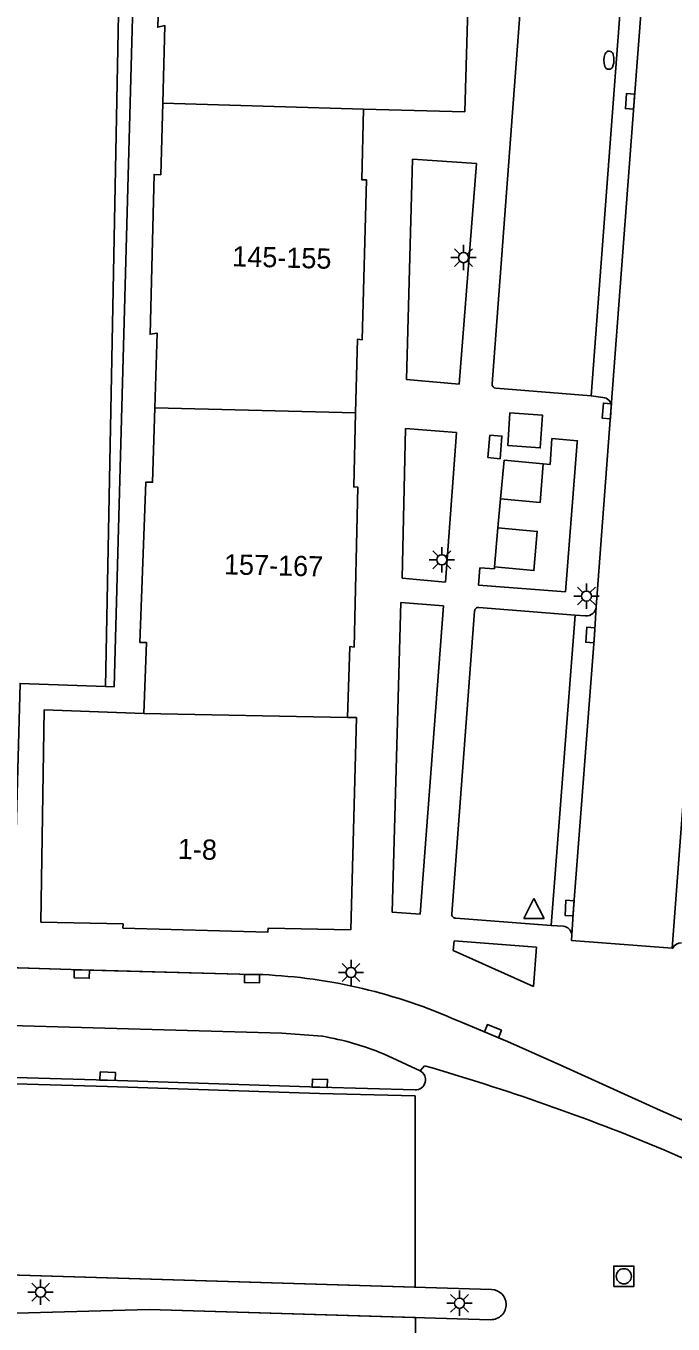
# Model space of a CAD drawing. Extents: x 132573 to 132944, y 398226 to 398676.
# Drawn here: x 132785.5 to 132817.6, y 398277.6 to 398341.8 of the extents above; entities that cross this region are included whole.
import ezdxf

# ---------------------------------------------------------------- set-up
doc = ezdxf.new("R2010")
doc.units = 0
for name, color, linetype in [('gg-anno-huisnummerreeks BGT', 7, 'Continuous'), ('gg-bbg-hoofdgebouw', 7, 'Continuous'), ('gg-bbg-tussenscheiding', 7, 'Continuous'), ('gg-knt-verharding', 7, 'Continuous'), ('gg-knt-verharding nz', 7, 'Continuous'), ('gg-kwrk-afval apart plaats', 7, 'Continuous'), ('gt-grn-groengrens', 7, 'Continuous'), ('gt-symb-brandkraan', 7, 'Continuous'), ('gt-symb-kolk', 7, 'Continuous'), ('gt-symb-lichtmast', 7, 'Continuous'), ('gt-symb-rioolschacht', 7, 'Continuous'), ('gt-symb-waterafsluiter', 7, 'Continuous'), ('ir-asfa-asfalt arcering', 7, 'Continuous'), ('ir-asfa-asfalt rood', 7, 'Continuous')]:
    doc.layers.add(name, color=color, linetype=linetype)

msp = doc.modelspace()

# ---------------------------------------------------------------- linework, layer by layer
at = {"layer": 'gg-bbg-hoofdgebouw'}
for p, q in [((132807.26, 398337.57), (132807.56, 398348.04)), ((132802.25, 398337.71), (132807.26, 398337.57))]:
    msp.add_line(p, q, dxfattribs=at)
for points in [[(132798.495, 398348.532), (132796.16, 398348.6), (132796.15, 398348.37), (132792.26, 398348.48), (132792.06, 398341.76), (132792.42, 398341.84), (132792.311, 398338)], [(132792.311, 398338), (132792.21, 398334.47), (132791.88, 398334.48), (132791.68, 398326.58), (132792.03, 398326.64), (132791.92, 398322.944)], [(132801.855, 398322.685), (132801.95, 398326.34), (132802.18, 398326.31), (132802.39, 398334.22), (132802.16, 398334.22), (132802.25, 398337.71)], [(132791.92, 398322.944), (132791.81, 398319.26), (132791.48, 398319.27), (132791.18, 398311.34), (132791.51, 398311.33), (132791.38, 398307.82)], [(132801.45, 398307.63), (132801.57, 398311.13), (132801.78, 398311.11), (132801.96, 398319.02), (132801.76, 398319.03), (132801.855, 398322.685)], [(132791.38, 398307.82), (132786.44, 398308), (132786.28, 398297.5)], [(132801.45, 398307.63), (132801.89, 398307.62), (132801.61, 398297.12)], [(132801.61, 398297.12), (132797.53, 398297.21), (132797.51, 398297.01), (132790.34, 398297.21), (132790.35, 398297.42), (132786.28, 398297.5)]]:
    msp.add_lwpolyline(points, dxfattribs=at)
at = {"layer": 'gg-bbg-tussenscheiding'}
for p, q in [((132792.311, 398338), (132802.25, 398337.71)), ((132801.855, 398322.685), (132791.92, 398322.944)), ((132801.45, 398307.63), (132791.38, 398307.82))]:
    msp.add_line(p, q, dxfattribs=at)
at = {"layer": 'gg-knt-verharding'}
for p, q in [((132808.606, 398324.128), (132810.414, 398348.064)), ((132807.835, 398335.016), (132806.983, 398324.106)), ((132806.983, 398324.106), (132804.368, 398324.337)), ((132813.517, 398323.528), (132808.787, 398323.908)), ((132814.086, 398323.443), (132813.517, 398323.528)), ((132813.756, 398313.104), (132814.506, 398323.009)), ((132804.151, 398314.509), (132804.321, 398321.924)), ((132804.321, 398321.924), (132806.853, 398321.727)), ((132806.853, 398321.727), (132806.303, 398314.323)), ((132808.394, 398320.477), (132808.49, 398321.585)), ((132809.011, 398320.425), (132808.394, 398320.477)), ((132809.027, 398318.444), (132809.197, 398320.346)), ((132808.897, 398317.005), (132809.027, 398318.444)), ((132808.727, 398315.078), (132808.897, 398317.005)), ((132807.929, 398314.169), (132807.993, 398315.03)), ((132806.303, 398314.323), (132804.151, 398314.509)), ((132804.083, 398313.316), (132806.194, 398313.148)), ((132806.194, 398313.148), (132805.042, 398297.892)), ((132806.613, 398297.913), (132807.74, 398312.883)), ((132807.954, 398313.068), (132812.714, 398312.686)), ((132812.714, 398312.686), (132813.237, 398312.652)), ((132811.531, 398297.341), (132806.806, 398297.697)), ((132812.122, 398297.307), (132811.531, 398297.341)), ((132812.542, 398296.601), (132812.556, 398296.871)), ((132806.738, 398296.584), (132806.686, 398296.101)), ((132810.809, 398296.265), (132806.738, 398296.584)), ((132810.655, 398294.324), (132810.809, 398296.265)), ((132817.512, 398296.226), (132812.542, 398296.601)), ((132817.546, 398296.223), (132817.512, 398296.226)), ((132806.686, 398296.101), (132810.655, 398294.324)), ((132803.229, 398290.985), (132805.05, 398290.153)), ((132816.942, 398288.197), (132812.1, 398290.375)), ((132808.578, 398279.341), (132774.34, 398280.37))]:
    msp.add_line(p, q, dxfattribs=at)
for points in [[(132798.535, 398349.903), (132791.03, 398350.08), (132789.91, 398309.15), (132789.475, 398309.165)], [(132804.368, 398324.337), (132804.67, 398335.236), (132807.835, 398335.016)], [(132812.819, 398321.236), (132812.237, 398313.844), (132807.929, 398314.169)], [(132808.49, 398321.585), (132809.096, 398321.543), (132809.011, 398320.425)], [(132812.819, 398321.236), (132812.826, 398321.313), (132811.569, 398321.42), (132811.475, 398320.145), (132811.133, 398320.17)], [(132807.993, 398315.03), (132808.718, 398314.983), (132808.727, 398315.078)], [(132805.042, 398297.892), (132803.659, 398298.006), (132804.083, 398313.316)], [(132789.475, 398309.165), (132785.25, 398309.31), (132784.948, 398297.791)], [(132797.256, 398294.91), (132796.729, 398294.913), (132788.309, 398295.144), (132774.193, 398295.587)], [(132774.846, 398292.671), (132798.199, 398292.017), (132800.206, 398291.863)], [(132812.1, 398290.375), (132809.366, 398291.605), (132806.922, 398292.621)], [(132774.802, 398290.113), (132789.578, 398289.684), (132800.077, 398289.337), (132804.804, 398289.208)], [(132824.492, 398284.677), (132818.145, 398287.656), (132816.942, 398288.197)], [(132774.29, 398277.87), (132791.63, 398278.35), (132808.533, 398277.845)]]:
    msp.add_lwpolyline(points, dxfattribs=at)
for centre, radius, start, end in [((132808.816, 398324.116), 0.21, 176.82394, 262.06619), ((132814.089, 398323.026), 0.417, 357.66363, 90.45799), ((132807.932, 398312.877), 0.192, 83.43793, 178.24798), ((132813.268, 398313.14), 0.489, 266.33665, 355.76893), ((132806.807, 398297.893), 0.196, 173.99977, 269.56299), ((132812.063, 398296.814), 0.496, 6.57919, 83.15738), ((132817.96, 398296.018), 0.462, 87.45576, 153.69382), ((132796.078, 398268.383), 26.553, 65.89662, 87.45786), ((132797.925, 398278.365), 13.69, 67.20244, 80.40674), ((132804.809, 398289.711), 0.503, 269.45289, 61.36461), ((132808.554, 398278.592), 0.749, 2.1288, 88.18819), ((132808.554, 398278.594), 0.749, 268.35794, 2.0129)]:
    msp.add_arc(centre, radius, start, end, dxfattribs=at)
at = {"layer": 'gg-knt-verharding nz'}
for p, q in [((132813.517, 398323.528), (132815.337, 398347.889)), ((132817.512, 398296.226), (132818.81, 398313.33)), ((132811.531, 398297.341), (132812.714, 398312.686)), ((132805.05, 398290.153), (132805.266, 398290.404)), ((132817.108, 398286.251), (132822.579, 398283.821))]:
    msp.add_line(p, q, dxfattribs=at)
for points in [[(132814.506, 398323.009), (132815.632, 398338.083), (132816.386, 398347.808)], [(132812.556, 398296.871), (132812.637, 398298.186), (132813.667, 398311.69), (132813.756, 398313.104)]]:
    msp.add_lwpolyline(points, dxfattribs=at)
msp.add_arc((132773.592, 398181.128), 113.774, 67.51276, 73.83561, dxfattribs=at)
at = {"layer": 'gg-kwrk-afval apart plaats'}
msp.add_line((132809.197, 398320.346), (132811.133, 398320.17), dxfattribs=at)
for points in [[(132809.492, 398322.687), (132811.105, 398322.574), (132810.989, 398320.96), (132809.379, 398321.079), (132809.492, 398322.687)], [(132811.133, 398320.17), (132810.99, 398318.266), (132809.027, 398318.444)], [(132808.727, 398315.078), (132810.679, 398314.895), (132810.838, 398316.829), (132808.897, 398317.005)]]:
    msp.add_lwpolyline(points, dxfattribs=at)
at = {"layer": 'gt-grn-groengrens'}
msp.add_line((132790.288, 398350.798), (132789.475, 398309.165), dxfattribs=at)
at = {"layer": 'gt-symb-brandkraan'}
for centre, radius, start, end in [((132814.396, 398340.374), 0.206, 15.97693, 160.84307), ((132815.079, 398340.111), 0.938, 161.51797, 195.30203), ((132817.069, 398340.655), 3, 195.30203, 195.97692), ((132814.382, 398339.886), 0.206, 195.97692, 340.84305), ((132817.035, 398339.457), 3, 160.84307, 161.51797), ((132811.743, 398340.803), 3, 340.84305, 341.51795), ((132813.699, 398340.149), 0.938, 341.51795, 15.30204), ((132811.709, 398339.605), 3, 15.30204, 15.97693)]:
    msp.add_arc(centre, radius, start, end, dxfattribs=at)
at = {"layer": 'gt-symb-kolk'}
for points in [[(132815.632, 398338.083), (132815.66, 398338.457), (132815.261, 398338.487), (132815.205, 398337.739), (132815.604, 398337.709), (132815.632, 398338.083)], [(132814.487, 398322.77), (132814.515, 398323.144), (132814.116, 398323.174), (132814.06, 398322.426), (132814.459, 398322.396), (132814.487, 398322.77)], [(132813.667, 398311.69), (132813.696, 398312.064), (132813.297, 398312.094), (132813.24, 398311.347), (132813.638, 398311.316), (132813.667, 398311.69)], [(132812.637, 398298.186), (132812.66, 398298.56), (132812.261, 398298.585), (132812.215, 398297.836), (132812.614, 398297.812), (132812.637, 398298.186)], [(132788.309, 398295.144), (132787.934, 398295.154), (132787.923, 398294.754), (132788.673, 398294.734), (132788.684, 398295.134), (132788.309, 398295.144)], [(132796.729, 398294.913), (132796.354, 398294.915), (132796.352, 398294.515), (132797.102, 398294.511), (132797.104, 398294.911), (132796.729, 398294.913)], [(132808.573, 398291.931), (132808.92, 398291.789), (132809.072, 398292.159), (132808.378, 398292.443), (132808.226, 398292.073), (132808.573, 398291.931)], [(132789.578, 398289.684), (132789.953, 398289.673), (132789.965, 398290.073), (132789.215, 398290.095), (132789.203, 398289.695), (132789.578, 398289.684)], [(132800.077, 398289.337), (132800.452, 398289.327), (132800.463, 398289.727), (132799.713, 398289.747), (132799.702, 398289.347), (132800.077, 398289.337)]]:
    msp.add_lwpolyline(points, dxfattribs=at)
at = {"layer": 'gt-symb-lichtmast'}
for p, q in [((132807.192, 398330.617), (132807.192, 398330.992)), ((132806.942, 398330.367), (132806.567, 398330.367)), ((132807.015, 398330.544), (132806.75, 398330.809)), ((132807.015, 398330.19), (132806.75, 398329.925)), ((132807.369, 398330.544), (132807.634, 398330.809)), ((132807.634, 398329.925), (132807.369, 398330.19)), ((132807.442, 398330.367), (132807.817, 398330.367)), ((132807.192, 398330.117), (132807.192, 398329.742)), ((132805.867, 398315.422), (132805.492, 398315.422)), ((132805.94, 398315.599), (132805.675, 398315.864)), ((132806.117, 398315.672), (132806.117, 398316.047)), ((132806.294, 398315.599), (132806.559, 398315.864)), ((132806.367, 398315.422), (132806.742, 398315.422)), ((132805.94, 398315.245), (132805.675, 398314.98)), ((132806.117, 398315.172), (132806.117, 398314.797)), ((132806.559, 398314.98), (132806.294, 398315.245)), ((132813.274, 398313.881), (132813.274, 398314.256)), ((132813.024, 398313.631), (132812.649, 398313.631)), ((132813.097, 398313.808), (132812.832, 398314.073)), ((132813.451, 398313.808), (132813.716, 398314.073)), ((132813.524, 398313.631), (132813.899, 398313.631)), ((132813.097, 398313.454), (132812.832, 398313.189)), ((132813.274, 398313.381), (132813.274, 398313.006)), ((132813.716, 398313.189), (132813.451, 398313.454)), ((132801.625, 398295.262), (132801.625, 398295.637)), ((132801.375, 398295.012), (132801, 398295.012)), ((132801.448, 398295.189), (132801.183, 398295.454)), ((132801.802, 398295.189), (132802.067, 398295.454)), ((132801.875, 398295.012), (132802.25, 398295.012)), ((132801.448, 398294.835), (132801.183, 398294.57)), ((132801.625, 398294.762), (132801.625, 398294.387)), ((132802.067, 398294.57), (132801.802, 398294.835)), ((132786.089, 398279.385), (132785.824, 398279.65)), ((132786.266, 398279.458), (132786.266, 398279.833)), ((132786.443, 398279.385), (132786.708, 398279.65)), ((132786.016, 398279.208), (132785.641, 398279.208)), ((132786.089, 398279.031), (132785.824, 398278.766)), ((132786.266, 398278.958), (132786.266, 398278.583)), ((132786.708, 398278.766), (132786.443, 398279.031)), ((132786.516, 398279.208), (132786.891, 398279.208)), ((132806.821, 398278.833), (132806.556, 398279.098)), ((132806.998, 398278.906), (132806.998, 398279.281)), ((132807.175, 398278.833), (132807.44, 398279.098)), ((132806.748, 398278.656), (132806.373, 398278.656)), ((132806.821, 398278.479), (132806.556, 398278.214)), ((132806.998, 398278.406), (132806.998, 398278.031)), ((132807.44, 398278.214), (132807.175, 398278.479)), ((132807.248, 398278.656), (132807.623, 398278.656))]:
    msp.add_line(p, q, dxfattribs=at)
for centre in [(132807.192, 398330.367), (132806.117, 398315.422), (132813.274, 398313.631), (132801.625, 398295.012), (132786.266, 398279.208), (132806.998, 398278.656)]:
    msp.add_circle(centre, 0.25, dxfattribs=at)
at = {"layer": 'gt-symb-rioolschacht'}
msp.add_lwpolyline([(132814.628, 398279.493), (132815.628, 398279.493), (132815.628, 398280.493), (132814.628, 398280.493)], close=True, dxfattribs=at)
msp.add_circle((132815.128, 398279.993), 0.375, dxfattribs=at)
at = {"layer": 'gt-symb-waterafsluiter'}
for p, q in [((132810.18, 398297.68), (132810.68, 398298.68)), ((132810.68, 398298.68), (132811.18, 398297.68)), ((132811.18, 398297.68), (132810.18, 398297.68))]:
    msp.add_line(p, q, dxfattribs=at)
at = {"layer": 'ir-asfa-asfalt arcering'}
msp.add_lwpolyline([(132774.793, 398289.813), (132789.569, 398289.384), (132800.068, 398289.037), (132804.796, 398288.908), (132804.807, 398279.454), (132774.34, 398280.37), (132774.244, 398280.377), (132774.244, 398281.009), (132773.244, 398281.009), (132773.244, 398280.452), (132771.653, 398280.572), (132771.527, 398289.907)], close=True, dxfattribs=at)
for points in [[(132804.796, 398288.908), (132800.068, 398289.037), (132789.569, 398289.384), (132774.793, 398289.813)], [(132789.37, 398273.84), (132776.35, 398273.47), (132775.634, 398273.379), (132775.585, 398273.774), (132774.841, 398273.682), (132774.89, 398273.285), (132775.166, 398273.319), (132774.31, 398273.21), (132770.98, 398272.33), (132771.307, 398277.731), (132771.558, 398277.735), (132774.29, 398277.87), (132791.63, 398278.35), (132804.809, 398277.956), (132804.809, 398272.704), (132802.394, 398272.685), (132798.737, 398272.105), (132798.736, 398272.105), (132790.048, 398270.697), (132789.685, 398272.977), (132789.841, 398273.109), (132789.905, 398273.303)]]:
    msp.add_lwpolyline(points, dxfattribs=at)
at = {"layer": 'ir-asfa-asfalt rood'}
msp.add_line((132822.579, 398283.821), (132817.108, 398286.251), dxfattribs=at)
for points in [[(132774.193, 398295.587), (132775.309, 398295.552), (132775.297, 398295.157), (132776.046, 398295.133), (132776.059, 398295.528), (132788.309, 398295.144), (132787.934, 398295.154), (132787.923, 398294.754), (132788.673, 398294.734), (132788.684, 398295.134), (132796.729, 398294.913), (132796.354, 398294.915), (132796.352, 398294.515), (132797.102, 398294.511), (132797.104, 398294.911), (132797.256, 398294.91)], [(132800.206, 398291.863), (132798.199, 398292.017), (132774.846, 398292.671), (132772.181, 398292.738)], [(132806.922, 398292.621), (132808.228, 398292.078), (132808.226, 398292.073), (132808.92, 398291.789), (132808.921, 398291.79), (132809.366, 398291.605), (132812.1, 398290.375), (132816.942, 398288.197), (132818.145, 398287.656), (132824.492, 398284.677)], [(132805.266, 398290.404), (132805.05, 398290.153), (132803.229, 398290.985)]]:
    msp.add_lwpolyline(points, dxfattribs=at)
for centre, radius, start, end in [((132796.078, 398268.383), 26.553, 65.89662, 87.45786), ((132797.925, 398278.365), 13.69, 67.20244, 80.40674), ((132773.592, 398181.128), 113.774, 67.51276, 73.83561)]:
    msp.add_arc(centre, radius, start, end, dxfattribs=at)

# ---------------------------------------------------------------- texts
at = {"layer": 'gg-anno-huisnummerreeks BGT'}
for s, rotation, p in [('145-155', 358.5, (132795.739, 398329.94)), ('157-167', 358.7, (132795.33, 398314.706)), ('1-8', 358.4, (132793.046, 398300.635))]:
    msp.add_text(s, height=1, rotation=rotation, dxfattribs=at).set_placement(p)

doc.saveas('drawing.dxf')
